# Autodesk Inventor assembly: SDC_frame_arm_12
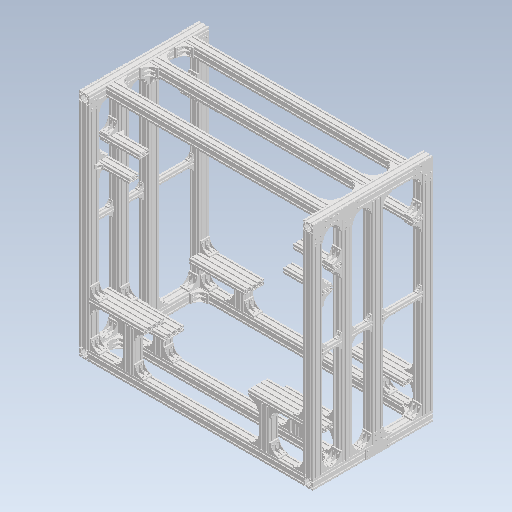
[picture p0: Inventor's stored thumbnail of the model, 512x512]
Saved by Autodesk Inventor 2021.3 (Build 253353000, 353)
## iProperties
Created: 2022-02
Part Number: SDC_frame_arm_12
Description: CAx-IF Rec.Pracs.---Model Styling and Organization---1.2---2011-12-15
Document SubType Name: Assembly
Designer: kengo
Sending System: 3D_Kernel_IO2017 Sp2 by CT CoreTechnologie
Preprocessor: STEP Interface 2017 Sp2 by CT CoreTechnologie
Title: SDC_frame_arm_12.stp
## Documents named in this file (150)
- C:\Users\kengo\Documents\S2S_frame\SDC345\frame_misumi_ver12\SDC_frame_arm_12.iam
- C:\Users\kengo\Documents\S2S_frame\SDC345\frame_misumi_ver12\HBLFSDW8-90-SET(1).iam
- C:\Users\kengo\Documents\S2S_frame\SDC345\frame_misumi_ver12\HBLFSDW8-90-SET(2).iam
- C:\Users\kengo\Documents\S2S_frame\SDC345\frame_misumi_ver12\HBLFSDW8-90-SET(3).iam
- C:\Users\kengo\Documents\S2S_frame\SDC345\frame_misumi_ver12\HBLFSDW8-90-SET(4).iam
- C:\Users\kengo\Documents\S2S_frame\SDC345\frame_misumi_ver12\HBLFSDW8-90-SET(5).iam
- C:\Users\kengo\Documents\S2S_frame\SDC345\frame_misumi_ver12\HBLFSDW8-90-SET(6).iam
- C:\Users\kengo\Documents\S2S_frame\SDC345\frame_misumi_ver12\HBLFSDW8-90-SET(7).iam
- C:\Users\kengo\Documents\S2S_frame\SDC345\frame_misumi_ver12\HBLFSDW8-90-SET(8).iam
- C:\Users\kengo\Documents\S2S_frame\SDC345\frame_misumi_ver12\HBLFSDW8-90-SET(9).iam
- C:\Users\kengo\Documents\S2S_frame\SDC345\frame_misumi_ver12\HBLFSDW8-90-SET(10).iam
- C:\Users\kengo\Documents\S2S_frame\SDC345\frame_misumi_ver12\HBLFSDW8-90-SET(11).iam
- C:\Users\kengo\Documents\S2S_frame\SDC345\frame_misumi_ver12\HBLFSDW8-90-SET(12).iam
- C:\Users\kengo\Documents\S2S_frame\SDC345\frame_misumi_ver12\HBLFSDW8-90-SET(13).iam
- C:\Users\kengo\Documents\S2S_frame\SDC345\frame_misumi_ver12\HBLFSDW8-90-SET(14).iam
- C:\Users\kengo\Documents\S2S_frame\SDC345\frame_misumi_ver12\HBLFSDW8-90-SET(15).iam
- C:\Users\kengo\Documents\S2S_frame\SDC345\frame_misumi_ver12\HBLFSDW8-90-SET(16).iam
- C:\Users\kengo\Documents\S2S_frame\SDC345\frame_misumi_ver12\HBLFSDW8-90-SET(17).iam
- C:\Users\kengo\Documents\S2S_frame\SDC345\frame_misumi_ver12\HBLFSDW8-90-SET(18).iam
- C:\Users\kengo\Documents\S2S_frame\SDC345\frame_misumi_ver12\HBLFSDW8-90-SET(19).iam
- C:\Users\kengo\Documents\S2S_frame\SDC345\frame_misumi_ver12\HBLFSDW8-90-SET(20).iam
- C:\Users\kengo\Documents\S2S_frame\SDC345\frame_misumi_ver12\HBLFSDW8-90-SET(21).iam
- C:\Users\kengo\Documents\S2S_frame\SDC345\frame_misumi_ver12\GNFS8-9090-1910.ipt
- C:\Users\kengo\Documents\S2S_frame\SDC345\frame_misumi_ver12\GNFS8-9090-1940.ipt
- C:\Users\kengo\Documents\S2S_frame\SDC345\frame_misumi_ver12\GNFS8-9090-1090.ipt
- C:\Users\kengo\Documents\S2S_frame\SDC345\frame_misumi_ver12\HBLFSDW8-90-SET(22).iam
- C:\Users\kengo\Documents\S2S_frame\SDC345\frame_misumi_ver12\HPTTD8-45-SET(1).iam
- C:\Users\kengo\Documents\S2S_frame\SDC345\frame_misumi_ver12\HPTTD8-45-SET(2).iam
- C:\Users\kengo\Documents\S2S_frame\SDC345\frame_misumi_ver12\HPTTD8-45-SET(3).iam
- C:\Users\kengo\Documents\S2S_frame\SDC345\frame_misumi_ver12\HPTLD8-45-SET(1).iam
- C:\Users\kengo\Documents\S2S_frame\SDC345\frame_misumi_ver12\HPTLD8-45-SET(2).iam
- C:\Users\kengo\Documents\S2S_frame\SDC345\frame_misumi_ver12\HPTTD8-45-SET(4).iam
- C:\Users\kengo\Documents\S2S_frame\SDC345\frame_misumi_ver12\HPTLD8-45-SET(3).iam
- C:\Users\kengo\Documents\S2S_frame\SDC345\frame_misumi_ver12\HPTLD8-45-SET(4).iam
- C:\Users\kengo\Documents\S2S_frame\SDC345\frame_misumi_ver12\HBLFSDW8-90-SET(23).iam
- C:\Users\kengo\Documents\S2S_frame\SDC345\frame_misumi_ver12\HBLFSDW8-90-SET(24).iam
- C:\Users\kengo\Documents\S2S_frame\SDC345\frame_misumi_ver12\HBLFSDW8-90-SET(25).iam
- C:\Users\kengo\Documents\S2S_frame\SDC345\frame_misumi_ver12\HBLFSDW8-90-SET(26).iam
- C:\Users\kengo\Documents\S2S_frame\SDC345\frame_misumi_ver12\HBLFSDW8-90-SET(27).iam
- C:\Users\kengo\Documents\S2S_frame\SDC345\frame_misumi_ver12\HBLFSDW8-90-SET(28).iam
- C:\Users\kengo\Documents\S2S_frame\SDC345\frame_misumi_ver12\HBLFSDW8-90-SET(29).iam
- C:\Users\kengo\Documents\S2S_frame\SDC345\frame_misumi_ver12\HBLFSDW8-90-SET(30).iam
- C:\Users\kengo\Documents\S2S_frame\SDC345\frame_misumi_ver12\HBLFSDW8-90-SET(31).iam
- C:\Users\kengo\Documents\S2S_frame\SDC345\frame_misumi_ver12\HBLFSDW8-90-SET(32).iam
- C:\Users\kengo\Documents\S2S_frame\SDC345\frame_misumi_ver12\HBLFSDW8-90-SET(33).iam
- C:\Users\kengo\Documents\S2S_frame\SDC345\frame_misumi_ver12\HBLFSDW8-90-SET(34).iam
- C:\Users\kengo\Documents\S2S_frame\SDC345\frame_misumi_ver12\HBLFSDW8-90-SET(35).iam
- C:\Users\kengo\Documents\S2S_frame\SDC345\frame_misumi_ver12\HBLFSDW8-90-SET(36).iam
- C:\Users\kengo\Documents\S2S_frame\SDC345\frame_misumi_ver12\HBLFSDW8-90-SET(37).iam
- C:\Users\kengo\Documents\S2S_frame\SDC345\frame_misumi_ver12\HBLFSDW8-90-SET(38).iam
- C:\Users\kengo\Documents\S2S_frame\SDC345\frame_misumi_ver12\HBLFSDW8-90-SET(39).iam
- C:\Users\kengo\Documents\S2S_frame\SDC345\frame_misumi_ver12\HBLFSDW8-90-SET(40).iam
- C:\Users\kengo\Documents\S2S_frame\SDC345\frame_misumi_ver12\HBLFSDW8-90-SET(41).iam
- C:\Users\kengo\Documents\S2S_frame\SDC345\frame_misumi_ver12\HBLFSDW8-90-SET(42).iam
- C:\Users\kengo\Documents\S2S_frame\SDC345\frame_misumi_ver12\HBLFSDW8-90-SET(43).iam
- C:\Users\kengo\Documents\S2S_frame\SDC345\frame_misumi_ver12\HBLFSDW8-90-SET(44).iam
- C:\Users\kengo\Documents\S2S_frame\SDC345\frame_misumi_ver12\HPTSD8-45-SET(1).iam
- C:\Users\kengo\Documents\S2S_frame\SDC345\frame_misumi_ver12\HBLFSDW8-90-SET(45).iam
- C:\Users\kengo\Documents\S2S_frame\SDC345\frame_misumi_ver12\HPTSD8-45-SET(2).iam
- C:\Users\kengo\Documents\S2S_frame\SDC345\frame_misumi_ver12\HPTSD8-45-SET(3).iam
- C:\Users\kengo\Documents\S2S_frame\SDC345\frame_misumi_ver12\HPTSD8-45-SET(4).iam
- C:\Users\kengo\Documents\S2S_frame\SDC345\frame_misumi_ver12\GNFS8-4590-360-RTP.ipt
- C:\Users\kengo\Documents\S2S_frame\SDC345\frame_misumi_ver12\HBLFSDW8-90-SET(46).iam
- C:\Users\kengo\Documents\S2S_frame\SDC345\frame_misumi_ver12\HBLFSDW8-90-SET(47).iam
- C:\Users\kengo\Documents\S2S_frame\SDC345\frame_misumi_ver12\HBLFSDW8-90-SET(48).iam
- C:\Users\kengo\Documents\S2S_frame\SDC345\frame_misumi_ver12\HBLFSDW8-90-SET(49).iam
- C:\Users\kengo\Documents\S2S_frame\SDC345\frame_misumi_ver12\HBLFSDW8-90-SET(50).iam
- C:\Users\kengo\Documents\S2S_frame\SDC345\frame_misumi_ver12\GNFS8-4590-360-LTP.ipt
- C:\Users\kengo\Documents\S2S_frame\SDC345\frame_misumi_ver12\HBLFSN8-45-SET(1).iam
- C:\Users\kengo\Documents\S2S_frame\SDC345\frame_misumi_ver12\HBLFSDW8-90-SET(51).iam
- C:\Users\kengo\Documents\S2S_frame\SDC345\frame_misumi_ver12\HBLFSDW8-90-SET(52).iam
- C:\Users\kengo\Documents\S2S_frame\SDC345\frame_misumi_ver12\HBLFSDW8-90-SET(53).iam
- C:\Users\kengo\Documents\S2S_frame\SDC345\frame_misumi_ver12\GNFS8-4545-180.ipt
- C:\Users\kengo\Documents\S2S_frame\SDC345\frame_misumi_ver12\HBLFSN8-45-SET(2).iam
- C:\Users\kengo\Documents\S2S_frame\SDC345\frame_misumi_ver12\HBLFSN8-45-SET(3).iam
- C:\Users\kengo\Documents\S2S_frame\SDC345\frame_misumi_ver12\HBLFSN8-45-SET(4).iam
- C:\Users\kengo\Documents\S2S_frame\SDC345\frame_misumi_ver12\HBLFSN8-45-SET(5).iam
- C:\Users\kengo\Documents\S2S_frame\SDC345\frame_misumi_ver12\GNFS8-4545-185.ipt
- C:\Users\kengo\Documents\S2S_frame\SDC345\frame_misumi_ver12\HBLFSN8-45-SET(6).iam
- C:\Users\kengo\Documents\S2S_frame\SDC345\frame_misumi_ver12\HBLFSN8-45-SET(7).iam
- C:\Users\kengo\Documents\S2S_frame\SDC345\frame_misumi_ver12\HBLFSN8-45-SET(8).iam
- C:\Users\kengo\Documents\S2S_frame\SDC345\frame_misumi_ver12\HBLFSN8-45-SET(9).iam
- C:\Users\kengo\Documents\S2S_frame\SDC345\frame_misumi_ver12\GNFS8-4545-365.ipt
- C:\Users\kengo\Documents\S2S_frame\SDC345\frame_misumi_ver12\HBLFSN8-45-SET(10).iam
- C:\Users\kengo\Documents\S2S_frame\SDC345\frame_misumi_ver12\HBLFSN8-45-SET(11).iam
- C:\Users\kengo\Documents\S2S_frame\SDC345\frame_misumi_ver12\HBLFSN8-45-SET(12).iam
- C:\Users\kengo\Documents\S2S_frame\SDC345\frame_misumi_ver12\HBLFSN8-45-SET(13).iam
- C:\Users\kengo\Documents\S2S_frame\SDC345\frame_misumi_ver12\HBLFSN8-45-SET(14).iam
- C:\Users\kengo\Documents\S2S_frame\SDC345\frame_misumi_ver12\HBLFSN8-45-SET(15).iam
- C:\Users\kengo\Documents\S2S_frame\SDC345\frame_misumi_ver12\HBLFSN8-45-SET(16).iam
- C:\Users\kengo\Documents\S2S_frame\SDC345\frame_misumi_ver12\HBLFSN8-45-SET(17).iam
- C:\Users\kengo\Documents\S2S_frame\SDC345\frame_misumi_ver12\HBLFSN8-45-SET(18).iam
- C:\Users\kengo\Documents\S2S_frame\SDC345\frame_misumi_ver12\HBLFSN8-45-SET(19).iam
- C:\Users\kengo\Documents\S2S_frame\SDC345\frame_misumi_ver12\HBLFSN8-45-SET(20).iam
- C:\Users\kengo\Documents\S2S_frame\SDC345\frame_misumi_ver12\HBLFSN8-45-SET(21).iam
- C:\Users\kengo\Documents\S2S_frame\SDC345\frame_misumi_ver12\HBLFSN8-45-SET(22).iam
- C:\Users\kengo\Documents\S2S_frame\SDC345\frame_misumi_ver12\HBLFSN8-45-SET(23).iam
- C:\Users\kengo\Documents\S2S_frame\SDC345\frame_misumi_ver12\HBLFSN8-45-SET(24).iam
- C:\Users\kengo\Documents\S2S_frame\SDC345\frame_misumi_ver12\HBLFSN8-45-SET(25).iam
- C:\Users\kengo\Documents\S2S_frame\SDC345\frame_misumi_ver12\HBLFSN8-45-SET(26).iam
- C:\Users\kengo\Documents\S2S_frame\SDC345\frame_misumi_ver12\HBLFSN8-45-SET(27).iam
- C:\Users\kengo\Documents\S2S_frame\SDC345\frame_misumi_ver12\HBLFSN8-45-SET(28).iam
- C:\Users\kengo\Documents\S2S_frame\SDC345\frame_misumi_ver12\HBLFSDW8-90-SET(54).iam
- C:\Users\kengo\Documents\S2S_frame\SDC345\frame_misumi_ver12\HBLFSDW8-90-SET(55).iam
- C:\Users\kengo\Documents\S2S_frame\SDC345\frame_misumi_ver12\HFS8-45180-500.ipt
- C:\Users\kengo\Documents\S2S_frame\SDC345\frame_misumi_ver12\HBLFSDW8-90-SET(56).iam
- C:\Users\kengo\Documents\S2S_frame\SDC345\frame_misumi_ver12\HBLFSDW8-90-SET(57).iam
- C:\Users\kengo\Documents\S2S_frame\SDC345\frame_misumi_ver12\GNFS8-9090-225.ipt
- C:\Users\kengo\Documents\S2S_frame\SDC345\frame_misumi_ver12\HBLFSDW8-90-SET(58).iam
- C:\Users\kengo\Documents\S2S_frame\SDC345\frame_misumi_ver12\HBLFSDW8-90-SET(59).iam
- C:\Users\kengo\Documents\S2S_frame\SDC345\frame_misumi_ver12\HBLFSDW8-90-SET(60).iam
- C:\Users\kengo\Documents\S2S_frame\SDC345\frame_misumi_ver12\HBLFSDW8-90-SET(61).iam
- C:\Users\kengo\Documents\S2S_frame\SDC345\frame_misumi_ver12\HBLFSDW8-90-SET(62).iam
- C:\Users\kengo\Documents\S2S_frame\SDC345\frame_misumi_ver12\HBLFSDW8-90-SET(63).iam
- C:\Users\kengo\Documents\S2S_frame\SDC345\frame_misumi_ver12\HBLFSDW8-90-SET(64).iam
- C:\Users\kengo\Documents\S2S_frame\SDC345\frame_misumi_ver12\HBLFSDW8-90-SET(65).iam
- C:\Users\kengo\Documents\S2S_frame\SDC345\frame_misumi_ver12\HBLFSDW8-90-SET(66).iam
- C:\Users\kengo\Documents\S2S_frame\SDC345\frame_misumi_ver12\HBLFSDW8-90-SET(67).iam
- C:\Users\kengo\Documents\S2S_frame\SDC345\frame_misumi_ver12\HBLFSDW8-90-SET(68).iam
- C:\Users\kengo\Documents\S2S_frame\SDC345\frame_misumi_ver12\HBLFSDW8-90-SET(69).iam
- C:\Users\kengo\Documents\S2S_frame\SDC345\frame_misumi_ver12\HBLFSDW8-90-SET(70).iam
- C:\Users\kengo\Documents\S2S_frame\SDC345\frame_misumi_ver12\HBLFSDW8-90-SET(71).iam
- C:\Users\kengo\Documents\S2S_frame\SDC345\frame_misumi_ver12\HBLFSDW8-90-SET(72).iam
- C:\Users\kengo\Documents\S2S_frame\SDC345\frame_misumi_ver12\HBLFSDW8-90-SET(73).iam
- C:\Users\kengo\Documents\S2S_frame\SDC345\frame_misumi_ver12\HBLFSDW8-90-SET(74).iam
- C:\Users\kengo\Documents\S2S_frame\SDC345\frame_misumi_ver12\HBLFSDW8-90-SET(75).iam
- C:\Users\kengo\Documents\S2S_frame\SDC345\frame_misumi_ver12\HBLFSDW8-90-SET(76).iam
- C:\Users\kengo\Documents\S2S_frame\SDC345\frame_misumi_ver12\HBLFSDW8-90-SET(77).iam
- C:\Users\kengo\Documents\S2S_frame\SDC345\frame_misumi_ver12\HBLFSDW8-90-SET(78).iam
- C:\Users\kengo\Documents\S2S_frame\SDC345\frame_misumi_ver12\HBLFSDW8-90-SET(79).iam
- C:\Users\kengo\Documents\S2S_frame\SDC345\frame_misumi_ver12\GNFS8-9090-369.ipt
- C:\Users\kengo\Documents\S2S_frame\SDC345\frame_misumi_ver12\HBLFSDW8-90-SET(80).iam
- C:\Users\kengo\Documents\S2S_frame\SDC345\frame_misumi_ver12\HBLFSDW8-90-SET(81).iam
- C:\Users\kengo\Documents\S2S_frame\SDC345\frame_misumi_ver12\HBLFSDW8-90-SET(82).iam
- C:\Users\kengo\Documents\S2S_frame\SDC345\frame_misumi_ver12\HBLFSDW8-90-SET(83).iam
- C:\Users\kengo\Documents\S2S_frame\SDC345\frame_misumi_ver12\HBLFSDW8-90-SET(84).iam
- C:\Users\kengo\Documents\S2S_frame\SDC345\frame_misumi_ver12\HBLFSDW8-90-SET(85).iam
- C:\Users\kengo\Documents\S2S_frame\SDC345\frame_misumi_ver12\HBLFSDW8-90-SET(86).iam
- C:\Users\kengo\Documents\S2S_frame\SDC345\frame_misumi_ver12\HBLFSDW8-90-SET(87).iam
- C:\Users\kengo\Documents\S2S_frame\SDC345\frame_misumi_ver12\HBLFSDW8-90-SET(88).iam
- C:\Users\kengo\Documents\S2S_frame\SDC345\frame_misumi_ver12\HBLFSDW8-90-SET(89).iam
- C:\Users\kengo\Documents\S2S_frame\SDC345\frame_misumi_ver12\HBLFSN8-45-SET(29).iam
- C:\Users\kengo\Documents\S2S_frame\SDC345\frame_misumi_ver12\HBLFSN8-45-SET(30).iam
- C:\Users\kengo\Documents\S2S_frame\SDC345\frame_misumi_ver12\HBLFSDW8-90-SET(90).iam
- C:\Users\kengo\Documents\S2S_frame\SDC345\frame_misumi_ver12\HBLFSDW8-90-SET(91).iam
- C:\Users\kengo\Documents\S2S_frame\SDC345\frame_misumi_ver12\HBLFSDW8-90-SET(92).iam
- C:\Users\kengo\Documents\S2S_frame\SDC345\frame_misumi_ver12\HBLFSDW8-90-SET(93).iam
- C:\Users\kengo\Documents\S2S_frame\SDC345\frame_misumi_ver12\HBLFSDW8-90-SET(94).iam
- C:\Users\kengo\Documents\S2S_frame\SDC345\frame_misumi_ver12\HBLFSDW8-90-SET(95).iam
- C:\Users\kengo\Documents\S2S_frame\SDC345\frame_misumi_ver12\HBLFSDW8-90-SET(96).iam
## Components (180 placed, 149 different names)
1. HBLFSDW8-90-SET(1) [sub-assembly]
2. HBLFSDW8-90-SET(2) [sub-assembly]
3. HBLFSDW8-90-SET(3) [sub-assembly]
4. HBLFSDW8-90-SET(4) [sub-assembly]
5. HBLFSDW8-90-SET(5) [sub-assembly]
6. HBLFSDW8-90-SET(6) [sub-assembly]
7. HBLFSDW8-90-SET(7) [sub-assembly]
8. HBLFSDW8-90-SET(8) [sub-assembly]
9. HBLFSDW8-90-SET(9) [sub-assembly]
10. HBLFSDW8-90-SET(10) [sub-assembly]
11. HBLFSDW8-90-SET(11) [sub-assembly]
12. HBLFSDW8-90-SET(12) [sub-assembly]
13. HBLFSDW8-90-SET(13) [sub-assembly]
14. HBLFSDW8-90-SET(14) [sub-assembly]
15. HBLFSDW8-90-SET(15) [sub-assembly]
16. HBLFSDW8-90-SET(16) [sub-assembly]
17. HBLFSDW8-90-SET(17) [sub-assembly]
18. HBLFSDW8-90-SET(18) [sub-assembly]
19. HBLFSDW8-90-SET(19) [sub-assembly]
20. HBLFSDW8-90-SET(20) [sub-assembly]
21. HBLFSDW8-90-SET(21) [sub-assembly]
22. GNFS8-9090-1910
23. GNFS8-9090-1910:1
24. GNFS8-9090-1940
25. GNFS8-9090-1940:1
26. GNFS8-9090-1090 — フラッシュ:1, メイト:3, メイト:6
27. GNFS8-9090-1090:1 — メイト:1, フラッシュ:2, メイト:5, フラッシュ:5
28. GNFS8-9090-1940:2 — フラッシュ:1, メイト:1, フラッシュ:2, メイト:2, フラッシュ:3, メイト:4, フラッシュ:4, メイト:6
29. GNFS8-9090-1910:2
30. GNFS8-9090-1910:3
31. GNFS8-9090-1910:4
32. GNFS8-9090-1910:5 — フラッシュ:5
33. GNFS8-9090-1910:6
34. GNFS8-9090-1910:7
35. GNFS8-9090-1090:2
36. GNFS8-9090-1090:3
37. GNFS8-9090-1940:3
38. GNFS8-9090-1940:4
39. GNFS8-9090-1940:5
40. HBLFSDW8-90-SET(22) [sub-assembly]
41. HPTTD8-45-SET(1) [sub-assembly]
42. HPTTD8-45-SET(2) [sub-assembly]
43. HPTTD8-45-SET(3) [sub-assembly]
44. HPTLD8-45-SET(1) [sub-assembly]
45. HPTLD8-45-SET(2) [sub-assembly]
46. HPTTD8-45-SET(4) [sub-assembly]
47. HPTLD8-45-SET(3) [sub-assembly]
48. HPTLD8-45-SET(4) [sub-assembly]
49. HBLFSDW8-90-SET(23) [sub-assembly]
50. HBLFSDW8-90-SET(24) [sub-assembly]
51. HBLFSDW8-90-SET(25) [sub-assembly]
52. HBLFSDW8-90-SET(26) [sub-assembly]
53. HBLFSDW8-90-SET(27) [sub-assembly]
54. HBLFSDW8-90-SET(28) [sub-assembly]
55. HBLFSDW8-90-SET(29) [sub-assembly]
56. HBLFSDW8-90-SET(30) [sub-assembly]
57. HBLFSDW8-90-SET(31) [sub-assembly]
58. HBLFSDW8-90-SET(32) [sub-assembly]
59. HBLFSDW8-90-SET(33) [sub-assembly]
60. HBLFSDW8-90-SET(34) [sub-assembly]
61. HBLFSDW8-90-SET(35) [sub-assembly]
62. HBLFSDW8-90-SET(36) [sub-assembly]
63. HBLFSDW8-90-SET(37) [sub-assembly]
64. HBLFSDW8-90-SET(38) [sub-assembly]
65. HBLFSDW8-90-SET(39) [sub-assembly] — メイト:2, フラッシュ:3, メイト:3
66. HBLFSDW8-90-SET(40) [sub-assembly] — メイト:4, フラッシュ:4, メイト:5
67. HBLFSDW8-90-SET(41) [sub-assembly]
68. HBLFSDW8-90-SET(42) [sub-assembly]
69. HBLFSDW8-90-SET(43) [sub-assembly]
70. HBLFSDW8-90-SET(44) [sub-assembly]
71. HPTSD8-45-SET(1) [sub-assembly]
72. HBLFSDW8-90-SET(45) [sub-assembly]
73. HPTSD8-45-SET(2) [sub-assembly]
74. HPTSD8-45-SET(3) [sub-assembly]
75. HPTSD8-45-SET(4) [sub-assembly]
76. GNFS8-4590-360-RTP
77. HBLFSDW8-90-SET(46) [sub-assembly]
78. HBLFSDW8-90-SET(47) [sub-assembly]
79. GNFS8-4590-360-RTP:1
80. HBLFSDW8-90-SET(48) [sub-assembly]
81. HBLFSDW8-90-SET(49) [sub-assembly]
82. GNFS8-4590-360-RTP:2
83. HBLFSDW8-90-SET(50) [sub-assembly]
84. GNFS8-4590-360-LTP
85. GNFS8-4590-360-LTP:1
86. GNFS8-4590-360-LTP:2
87. HBLFSN8-45-SET(1) [sub-assembly]
88. HBLFSDW8-90-SET(51) [sub-assembly]
89. HBLFSDW8-90-SET(52) [sub-assembly]
90. HBLFSDW8-90-SET(53) [sub-assembly]
91. GNFS8-4545-180
92. HBLFSN8-45-SET(2) [sub-assembly]
93. HBLFSN8-45-SET(3) [sub-assembly]
94. HBLFSN8-45-SET(4) [sub-assembly]
95. HBLFSN8-45-SET(5) [sub-assembly]
96. GNFS8-4545-185
97. HBLFSN8-45-SET(6) [sub-assembly]
98. HBLFSN8-45-SET(7) [sub-assembly]
99. HBLFSN8-45-SET(8) [sub-assembly]
100. HBLFSN8-45-SET(9) [sub-assembly]
101. GNFS8-4545-365
102. HBLFSN8-45-SET(10) [sub-assembly]
103. HBLFSN8-45-SET(11) [sub-assembly]
104. HBLFSN8-45-SET(12) [sub-assembly]
105. HBLFSN8-45-SET(13) [sub-assembly]
106. GNFS8-4545-365:1
107. HBLFSN8-45-SET(14) [sub-assembly]
108. HBLFSN8-45-SET(15) [sub-assembly]
109. HBLFSN8-45-SET(16) [sub-assembly]
110. HBLFSN8-45-SET(17) [sub-assembly]
111. GNFS8-4545-185:1
112. HBLFSN8-45-SET(18) [sub-assembly]
113. HBLFSN8-45-SET(19) [sub-assembly]
114. HBLFSN8-45-SET(20) [sub-assembly]
115. HBLFSN8-45-SET(21) [sub-assembly]
116. GNFS8-4545-180:1
117. HBLFSN8-45-SET(22) [sub-assembly]
118. HBLFSN8-45-SET(23) [sub-assembly]
119. HBLFSN8-45-SET(24) [sub-assembly]
120. HBLFSN8-45-SET(25) [sub-assembly]
121. HBLFSN8-45-SET(26) [sub-assembly]
122. HBLFSN8-45-SET(27) [sub-assembly]
123. HBLFSN8-45-SET(28) [sub-assembly]
124. HBLFSDW8-90-SET(54) [sub-assembly]
125. HBLFSDW8-90-SET(55) [sub-assembly]
126. HFS8-45180-500
127. HBLFSDW8-90-SET(56) [sub-assembly]
128. HBLFSDW8-90-SET(57) [sub-assembly]
129. GNFS8-9090-225
130. HBLFSDW8-90-SET(58) [sub-assembly]
131. HBLFSDW8-90-SET(59) [sub-assembly]
132. HBLFSDW8-90-SET(60) [sub-assembly]
133. HFS8-45180-500:1
134. HBLFSDW8-90-SET(61) [sub-assembly]
135. HBLFSDW8-90-SET(62) [sub-assembly]
136. GNFS8-9090-225:1
137. HBLFSDW8-90-SET(63) [sub-assembly]
138. HBLFSDW8-90-SET(64) [sub-assembly]
139. HBLFSDW8-90-SET(65) [sub-assembly]
140. HBLFSDW8-90-SET(66) [sub-assembly]
141. HBLFSDW8-90-SET(67) [sub-assembly]
142. HFS8-45180-500:2
143. HBLFSDW8-90-SET(68) [sub-assembly]
144. HBLFSDW8-90-SET(69) [sub-assembly]
145. GNFS8-9090-225:2
146. HBLFSDW8-90-SET(70) [sub-assembly]
147. HBLFSDW8-90-SET(71) [sub-assembly]
148. HBLFSDW8-90-SET(72) [sub-assembly]
149. HFS8-45180-500:3
150. HBLFSDW8-90-SET(73) [sub-assembly]
151. HBLFSDW8-90-SET(74) [sub-assembly]
152. GNFS8-9090-225:3
153. HBLFSDW8-90-SET(75) [sub-assembly]
154. HBLFSDW8-90-SET(76) [sub-assembly]
155. HBLFSDW8-90-SET(77) [sub-assembly]
156. HBLFSDW8-90-SET(78) [sub-assembly]
157. HBLFSDW8-90-SET(79) [sub-assembly]
158. HFS8-45180-500:4
159. GNFS8-9090-369
160. HBLFSDW8-90-SET(80) [sub-assembly]
161. HBLFSDW8-90-SET(81) [sub-assembly]
162. HFS8-45180-500:5
163. GNFS8-9090-369:1
164. HBLFSDW8-90-SET(82) [sub-assembly]
165. HBLFSDW8-90-SET(83) [sub-assembly]
166. HBLFSDW8-90-SET(84) [sub-assembly]
167. HBLFSDW8-90-SET(85) [sub-assembly]
168. HBLFSDW8-90-SET(86) [sub-assembly]
169. HBLFSDW8-90-SET(87) [sub-assembly]
170. HBLFSDW8-90-SET(88) [sub-assembly]
171. HBLFSDW8-90-SET(89) [sub-assembly]
172. HBLFSN8-45-SET(29) [sub-assembly]
173. HBLFSN8-45-SET(30) [sub-assembly]
174. HBLFSDW8-90-SET(90) [sub-assembly]
175. HBLFSDW8-90-SET(91) [sub-assembly]
176. HBLFSDW8-90-SET(92) [sub-assembly]
177. HBLFSDW8-90-SET(93) [sub-assembly]
178. HBLFSDW8-90-SET(94) [sub-assembly]
179. HBLFSDW8-90-SET(95) [sub-assembly]
180. HBLFSDW8-90-SET(96) [sub-assembly]
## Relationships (11: Mate 6, Flush 5)
- フラッシュ:1 [Flush]: GNFS8-9090-1090 ↔ GNFS8-9090-1940:2
- メイト:1 [Mate]: GNFS8-9090-1090:1 ↔ GNFS8-9090-1940:2
- フラッシュ:2 [Flush]: GNFS8-9090-1090:1 ↔ GNFS8-9090-1940:2
- メイト:2 [Mate]: GNFS8-9090-1940:2 ↔ HBLFSDW8-90-SET(39)
- フラッシュ:3 [Flush]: GNFS8-9090-1940:2 ↔ HBLFSDW8-90-SET(39)
- メイト:3 [Mate]: GNFS8-9090-1090 ↔ HBLFSDW8-90-SET(39)
- メイト:4 [Mate]: GNFS8-9090-1940:2 ↔ HBLFSDW8-90-SET(40)
- フラッシュ:4 [Flush]: GNFS8-9090-1940:2 ↔ HBLFSDW8-90-SET(40)
- メイト:5 [Mate]: GNFS8-9090-1090:1 ↔ HBLFSDW8-90-SET(40)
- メイト:6 [Mate]: GNFS8-9090-1090 ↔ GNFS8-9090-1940:2
- フラッシュ:5 [Flush]: GNFS8-9090-1090:1 ↔ GNFS8-9090-1910:5
